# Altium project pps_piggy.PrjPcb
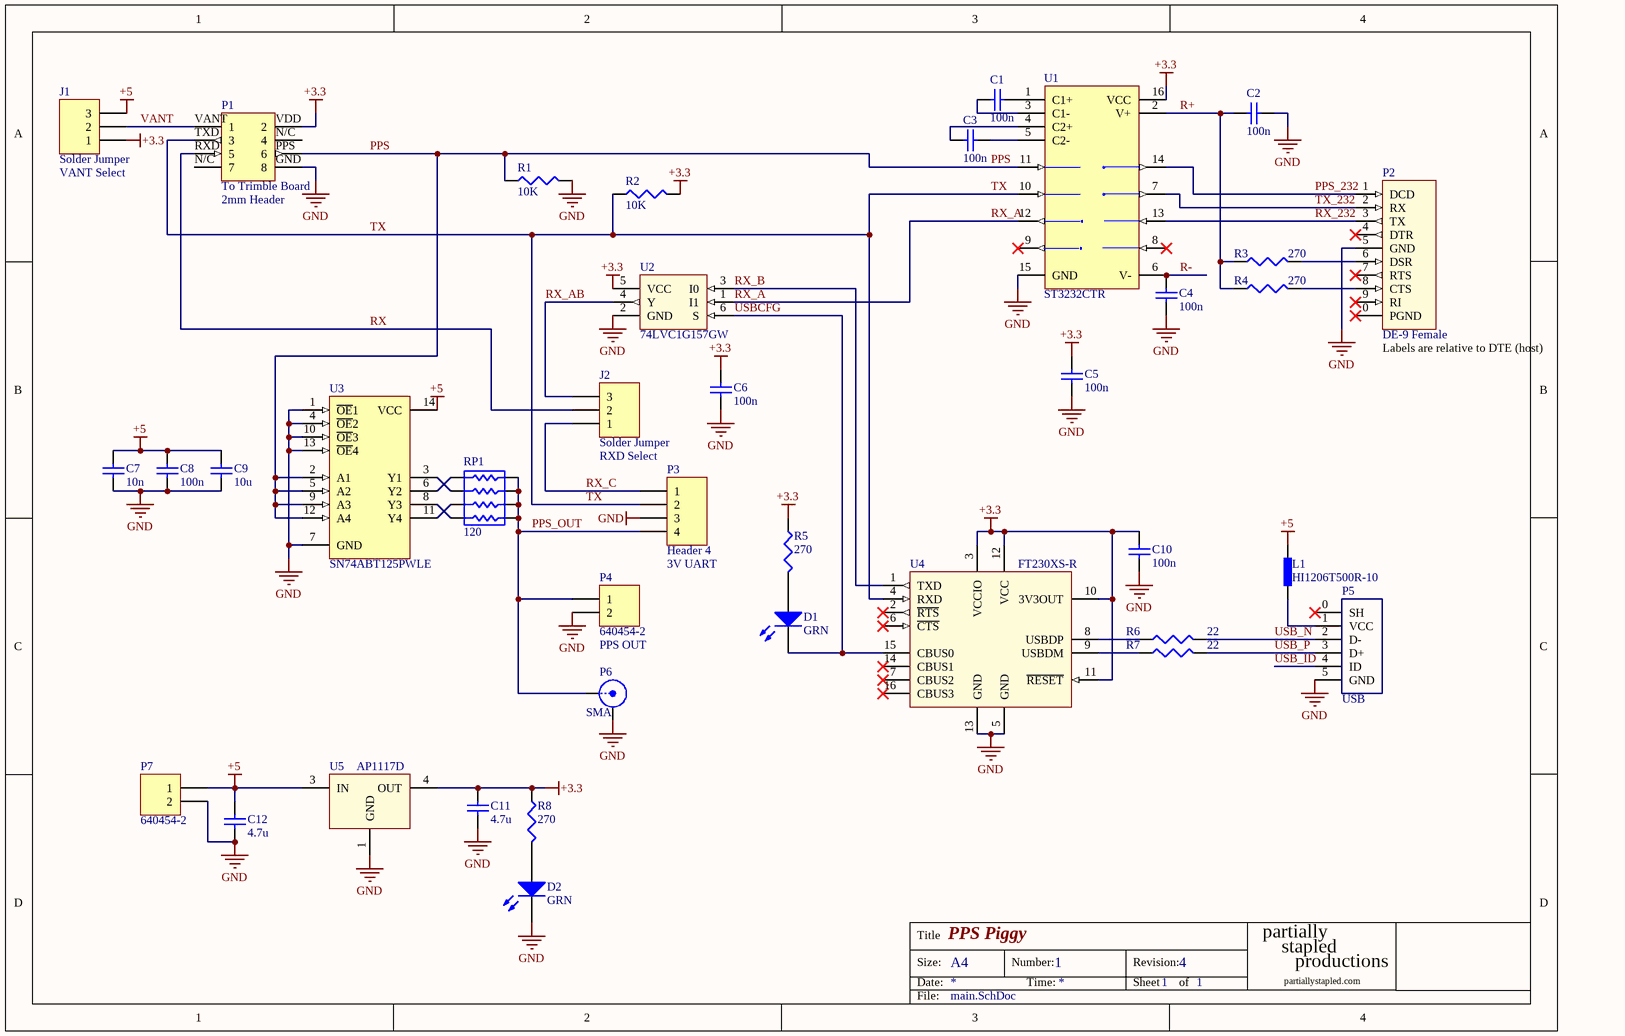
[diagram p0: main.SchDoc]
1 sheet, 38 parts. Net scope: global (net labels, ports and power ports of the same name join across sheets).
Board file: board.PcbDoc

## Sheet main.SchDoc: PPS Piggy
size A4; DocumentNumber: 1; Revision: 4; SheetNumber: 1; SheetTotal: 1

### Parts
C1  100n  [RESC1608N]
C2  100n  [RESC1608N]
C3  100n  [RESC1608N]
C4  100n  [RESC1608N]
C5  100n  [RESC1608N]
C6  100n  [RESC1608N]
C7  10n  [RESC1608N]
C8  100n  [RESC1608N]
C9  10u  [RESC2012N]
C10  100n  [RESC1608N]
C11  4.7u  [RESC2012N]
C12  4.7u  [RESC2012N]
D1  GRN  [DIO1608N]
D2  GRN  [DIO1608N]
J1  Solder Jumper  Label: VANT Select  [sol_jump_3]
J2  Solder Jumper  Label: RXD Select  [sol_jump_3]
L1  HI1206T500R-10  [RESC3216N]
P1  To Trimble Board  Type: 2mm Header  [NPPN042FFKS-RC_rev]
P2  DE-9 Female  [DE9_1734348]
P3  Header 4  Label: 3V UART  [HDR1X4]
P4  640454-2  Label: PPS OUT  [TEC_640454-2]
P5  USB  [0548190519]
P6  SMA  [SMA_COAX]
P7  640454-2  [TEC_640454-2]
R1  10K  [RESC1608N]
R2  10K  [RESC1608N]
R3  270  [RESC1608N]
R4  270  [RESC1608N]
R5  270  [RESC1608N]
R6  22  [RESC1608N]
R7  22  [RESC1608N]
R8  270  [RESC1608N]
RP1  120  [CRA06S]
U1  ST3232CTR  [TSSOP16_N]
U2  74LVC1G157GW  [SOT363-6N]
U3  SN74ABT125PWLE  [PW014_N]
U4  FT230XS-R  [SOP635P600-16N]
U5  AP1117D  [TO-252]

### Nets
+3.3: C5.2 C6.2 C10.2 C11.2 J1.1 P1.2 R2.1 R5.2 R8.2 U1.16(VCC) U2.5(VCC) U4.3(VCCIO) U4.10(3V3OUT) U4.11(~{RESET}) U4.12(VCC) U5.4(OUT)
+5: C7.2 C8.2 C9.2 C12.2 J1.3 L1.2 P7.1 U3.14(VCC) U5.3(IN)
GND: C2.1 C4.1 C5.1 C6.1 C7.1 C8.1 C9.1 C10.1 C11.1 C12.1 D2.2(K) P1.8 P2.5(GND) P3.3 P4.2 P5.5(GND) P6.2(Y) P7.2 R1.1 U1.15(GND) U2.2(GND) U3.1(~{OE}1) U3.4(~{OE}2) U3.7(GND) U3.10(~{OE}3) U3.13(~{OE}4) U4.5(GND) U4.13(GND) U5.1(GND)
PPS: P1.6 R1.2 U1.11(T1IN) U3.2(A1) U3.5(A2) U3.9(A3) U3.12(A4)
PPS_232: P2.1(DCD) U1.14(T1OUT)
PPS_OUT: P3.4 P4.1 P6.1(X) RP1.5 RP1.6 RP1.7 RP1.8
R+: C2.2 R3.2 R4.2 U1.2(V+)
R-: C4.2 U1.6(V-)
RX: J2.2 P1.5
RX_232: P2.3(TX) U1.13(R1IN)
RX_A: U1.12(R1OUT) U2.1(I1)
RX_AB: J2.3 U2.4(Y)
RX_B: U2.3(I0) U4.1(TXD)
RX_C: J2.1 P3.1
TX: P1.3 P3.2 R2.2 U1.10(T2IN) U4.4(RXD)
TX_232: P2.2(RX) U1.7(T2OUT)
USB_ID: P5.4(ID)
USB_N: P5.2(D-) R6.1
USB_P: P5.3(D+) R7.1
USBCFG: D1.2(K) U2.6(S) U4.15(CBUS0)
VANT: J1.2 P1.1
NetC1_1: C1.1 U1.1(C1+)
NetC1_2: C1.2 U1.3(C1-)
NetC3_1: C3.1 U1.5(C2-)
NetC3_2: C3.2 U1.4(C2+)
NetD1_1: D1.1(A) R5.1
NetD2_1: D2.1(A) R8.1
NetL1_1: L1.1 P5.1(VCC)
NetP2_6: P2.6(DSR) R3.1
NetP2_8: P2.8(CTS) R4.1
NetR6_2: R6.2 U4.8(USBDP)
NetR7_2: R7.2 U4.9(USBDM)
NetRP1_1: RP1.1 U3.6(Y2)
NetRP1_2: RP1.2 U3.3(Y1)
NetRP1_3: RP1.3 U3.11(Y4)
NetRP1_4: RP1.4 U3.8(Y3)

Not connected (* = marked no-connect by the designer): P1 4 7; P2 0(PGND)* 4(DTR)* 7(RTS)* 9(RI)*; P5 0(SH)*; U1 8(R2IN)* 9(R2OUT)*; U4 2(~{RTS})* 6(~{CTS})* 7(CBUS2)* 14(CBUS1)* 16(CBUS3)*

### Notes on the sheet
- (near P1) VANT
- (near P1) TXD
- (near P1) RXD
- (near P1) N/C
- (near P1) VDD
- (near P1) PPS
- (near P1) GND
- (near P2) Labels are relative to DTE (host)

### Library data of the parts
C1-C12 = Cap: Capacitor
D1 D2 = LED2: Typical RED, GREEN, YELLOW, AMBER GaAs LED
J1 J2 = Header 3: Header, 3-Pin
L1 = FerriteBead
P1 = Header 4X2: Header, 4-Pin, Dual row
P2 = SERIAL_DE9: DE-9 connector for RS-232
P3 = Header 4: Header, 4-Pin
P4 P7 = Header 2: Header, 2-Pin
P5 = USB OTG
P6 = BNC: BNC Elbow Connector
R1-R8 = Res_G: Resistor
RP1 = ResPack_4
U1 = MAX3232EEWE: ±15kV ESD-Protected, 3.0V to 5.5V, Low-Power, up to 250kbps, True RS-232 Transceiver
U3 = SN74ABT125PWLE: Quadruple Bus Buffer Gate with 3-State Outputs; ComponentAvailability: Obsolete
U5 = AP1117D: Low Dropout Regulator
